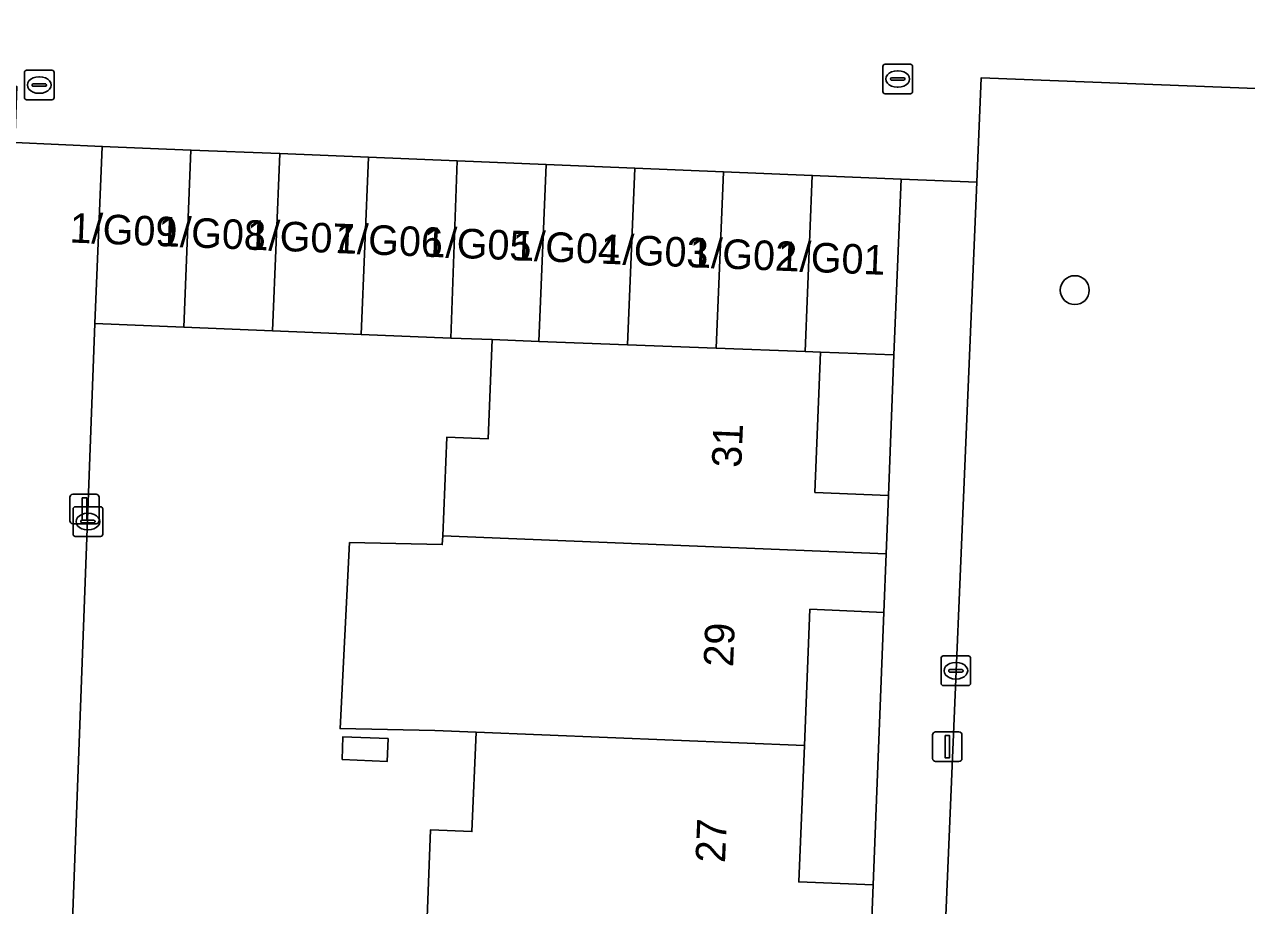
# Model space of a CAD drawing. Extents: x 160786 to 161429, y 386828 to 387485.
# Drawn here: x 160937.96 to 160979.3, y 387037.78 to 387067.6 of the extents above; entities that cross this region are included whole.
import ezdxf

# ---------------------------------------------------------------- set-up
doc = ezdxf.new("R2010")
doc.units = 0
for name, color, linetype in [('IMGEO_Boom', 7, 'Continuous'), ('IMGEO_Brandkraan', 7, 'Continuous'), ('IMGEO_Erf', 7, 'Continuous'), ('IMGEO_Groenvoorziening', 7, 'Continuous'), ('IMGEO_Kolk', 7, 'Continuous'), ('IMGEO_Lichtmast', 7, 'Continuous'), ('IMGEO_Pand', 7, 'Continuous'), ('IMGEO_Pand_nummerreeks', 7, 'Continuous'), ('IMGEO_Rijbaan_lokaal_open', 7, 'Continuous'), ('IMGEO_Rioolput', 7, 'Continuous'), ('IMGEO_Voetpad_open', 7, 'Continuous')]:
    doc.layers.add(name, color=color, linetype=linetype)

msp = doc.modelspace()

# ---------------------------------------------------------------- linework, layer by layer
at = {"layer": 'IMGEO_Boom'}
msp.add_circle((160973.488, 387058.606), 0.489, dxfattribs=at)
at = {"layer": 'IMGEO_Brandkraan'}
for p, q in [((160966.998, 387065.324), (160966.998, 387066.176)), ((160967.073, 387066.25), (160967.925, 387066.25)), ((160967.999, 387066.176), (160967.999, 387065.324)), ((160967.257, 387065.744), (160967.257, 387065.756)), ((160967.695, 387065.707), (160967.297, 387065.707)), ((160967.3, 387065.793), (160967.698, 387065.793)), ((160967.486, 387066.03), (160967.511, 387066.03)), ((160967.741, 387065.756), (160967.741, 387065.744)), ((160967.925, 387065.25), (160967.073, 387065.25)), ((160967.509, 387065.47), (160967.484, 387065.47))]:
    msp.add_line(p, q, dxfattribs=at)
for points in [[(160966.998, 387065.324), (160966.998, 387066.176)], [(160967.073, 387066.25), (160967.925, 387066.25)], [(160967.999, 387066.176), (160967.999, 387065.324)], [(160967.925, 387065.25), (160967.073, 387065.25)]]:
    msp.add_lwpolyline(points, dxfattribs=at)
for centre, radius, start, end in [((160967.075, 387066.174), 0.0765, 91.552, 178.448), ((160967.075, 387066.174), 0.0765, 91.552, 178.448), ((160967.923, 387066.174), 0.0765, 1.552, 88.448), ((160967.923, 387066.174), 0.0765, 1.552, 88.448), ((160967.297, 387065.753), 0.0403, 85.8775, 175.7526), ((160967.294, 387065.743), 0.0366, 178.938, 274.7102), ((160967.698, 387065.75), 0.043, 264.8664, 352.4533), ((160967.702, 387065.755), 0.0386, 1.7309, 96.639), ((160967.075, 387065.326), 0.0765, 181.552, 268.448), ((160967.075, 387065.326), 0.0765, 181.552, 268.448), ((160967.923, 387065.326), 0.0765, 271.552, 358.448), ((160967.923, 387065.326), 0.0765, 271.552, 358.448)]:
    msp.add_arc(centre, radius, start, end, dxfattribs=at)
for centre, major_axis, ratio, start_param, end_param in [((160967.485, 387065.75), (-0.387, 0.002), 0.722429, 4.712389, 7.853982), ((160967.51, 387065.75), (-0.39, 0.002), 0.717154, 1.570796, 4.712389)]:
    msp.add_ellipse(centre, major_axis=major_axis, ratio=ratio, start_param=start_param, end_param=end_param, dxfattribs=at)
at = {"layer": 'IMGEO_Erf'}
msp.add_lwpolyline([(160952.689, 387030.392), (160952.825, 387033.729), (160951.429, 387033.786), (160951.564, 387037.085), (160951.697, 387040.344), (160953.094, 387040.287), (160953.232, 387043.647), (160951.835, 387043.704), (160948.634, 387043.772), (160948.955, 387050.065), (160952.093, 387049.997), (160952.105, 387050.296), (160952.242, 387053.63), (160953.638, 387053.573), (160953.776, 387056.932), (160952.379, 387056.985), (160949.35, 387057.11), (160946.347, 387057.233), (160943.345, 387057.357), (160940.342, 387057.48), (160938.734, 387014.625), (160938.47, 387007.597)], dxfattribs=at)
for points in [[(160964.889, 387056.508), (160964.695, 387051.761), (160967.187, 387051.658), (160967.366, 387056.416)], [(160967.024, 387047.703), (160964.528, 387047.806), (160964.339, 387043.192), (160964.15, 387038.581), (160966.671, 387038.478)], [(160948.7, 387042.719), (160948.731, 387043.494), (160950.256, 387043.431), (160950.225, 387042.656)]]:
    msp.add_lwpolyline(points, close=True, dxfattribs=at)
at = {"layer": 'IMGEO_Groenvoorziening'}
msp.add_lwpolyline([(160981.974, 387001.361), (160984.552, 387065.241), (160970.32, 387065.784), (160970.17, 387062.263), (160967.621, 387001.944)], close=True, dxfattribs=at)
at = {"layer": 'IMGEO_Kolk'}
for p, q in [((160939.602, 387050.348), (160939.602, 387051.2)), ((160939.677, 387051.274), (160940.529, 387051.274)), ((160940.603, 387051.2), (160940.603, 387050.348)), ((160939.861, 387050.768), (160939.861, 387050.78)), ((160939.904, 387050.817), (160940.302, 387050.817)), ((160940.09, 387051.054), (160940.115, 387051.054)), ((160940.345, 387050.78), (160940.345, 387050.768)), ((160940.299, 387050.731), (160939.901, 387050.731)), ((160940.113, 387050.494), (160940.088, 387050.494)), ((160940.529, 387050.274), (160939.677, 387050.274)), ((160969.039, 387046.226), (160969.891, 387046.226)), ((160968.964, 387045.3), (160968.964, 387046.152)), ((160969.452, 387046.006), (160969.477, 387046.006)), ((160969.965, 387046.152), (160969.965, 387045.3)), ((160969.223, 387045.72), (160969.223, 387045.732)), ((160969.661, 387045.683), (160969.263, 387045.683)), ((160969.266, 387045.769), (160969.664, 387045.769)), ((160969.475, 387045.446), (160969.45, 387045.446)), ((160969.707, 387045.732), (160969.707, 387045.72)), ((160969.891, 387045.226), (160969.039, 387045.226))]:
    msp.add_line(p, q, dxfattribs=at)
for points in [[(160939.602, 387050.348), (160939.602, 387051.2)], [(160939.677, 387051.274), (160940.529, 387051.274)], [(160940.603, 387051.2), (160940.603, 387050.348)], [(160940.529, 387050.274), (160939.677, 387050.274)], [(160969.039, 387046.226), (160969.891, 387046.226)], [(160968.964, 387045.3), (160968.964, 387046.152)], [(160969.965, 387046.152), (160969.965, 387045.3)], [(160969.891, 387045.226), (160969.039, 387045.226)]]:
    msp.add_lwpolyline(points, dxfattribs=at)
for centre, radius, start, end in [((160939.679, 387051.198), 0.0765, 91.552, 178.448), ((160939.679, 387051.198), 0.0765, 91.552, 178.448), ((160940.527, 387051.198), 0.0765, 1.552, 88.448), ((160940.527, 387051.198), 0.0765, 1.552, 88.448), ((160939.901, 387050.777), 0.0403, 85.8775, 175.7526), ((160939.898, 387050.767), 0.0366, 178.938, 274.7102), ((160940.302, 387050.774), 0.043, 264.8664, 352.4533), ((160940.306, 387050.779), 0.0386, 1.7309, 96.639), ((160939.679, 387050.35), 0.0765, 181.552, 268.448), ((160939.679, 387050.35), 0.0765, 181.552, 268.448), ((160940.527, 387050.35), 0.0765, 271.552, 358.448), ((160940.527, 387050.35), 0.0765, 271.552, 358.448), ((160969.041, 387046.15), 0.0765, 91.552, 178.448), ((160969.041, 387046.15), 0.0765, 91.552, 178.448), ((160969.889, 387046.15), 0.0765, 1.552, 88.448), ((160969.889, 387046.15), 0.0765, 1.552, 88.448), ((160969.263, 387045.729), 0.0403, 85.8775, 175.7526), ((160969.26, 387045.719), 0.0366, 178.938, 274.7102), ((160969.664, 387045.726), 0.043, 264.8664, 352.4533), ((160969.668, 387045.731), 0.0386, 1.7309, 96.639), ((160969.041, 387045.302), 0.0765, 181.552, 268.448), ((160969.041, 387045.302), 0.0765, 181.552, 268.448), ((160969.889, 387045.302), 0.0765, 271.552, 358.448), ((160969.889, 387045.302), 0.0765, 271.552, 358.448)]:
    msp.add_arc(centre, radius, start, end, dxfattribs=at)
for centre, major_axis, ratio, start_param, end_param in [((160940.089, 387050.774), (-0.387, 0.002), 0.722429, 4.712389, 7.853982), ((160940.114, 387050.774), (-0.39, 0.002), 0.717154, 1.570796, 4.712389), ((160969.451, 387045.726), (-0.387, 0.002), 0.722429, 4.712389, 7.853982), ((160969.476, 387045.726), (-0.39, 0.002), 0.717154, 1.570796, 4.712389)]:
    msp.add_ellipse(centre, major_axis=major_axis, ratio=ratio, start_param=start_param, end_param=end_param, dxfattribs=at)
at = {"layer": 'IMGEO_Lichtmast'}
for p, q in [((160939.492, 387050.8), (160939.492, 387051.6)), ((160939.492, 387051.6), (160939.492, 387050.8)), ((160939.592, 387051.7), (160940.382, 387051.7)), ((160940.382, 387051.7), (160939.592, 387051.7)), ((160940.482, 387051.6), (160940.482, 387050.8)), ((160940.482, 387050.8), (160940.482, 387051.6)), ((160940.382, 387050.7), (160939.592, 387050.7)), ((160939.592, 387050.7), (160940.382, 387050.7)), ((160968.68, 387042.757), (160968.68, 387043.557)), ((160968.68, 387043.557), (160968.68, 387042.757)), ((160968.78, 387043.657), (160969.57, 387043.657)), ((160969.57, 387043.657), (160968.78, 387043.657)), ((160969.67, 387043.557), (160969.67, 387042.757)), ((160969.67, 387042.757), (160969.67, 387043.557)), ((160969.57, 387042.657), (160968.78, 387042.657)), ((160968.78, 387042.657), (160969.57, 387042.657))]:
    msp.add_line(p, q, dxfattribs=at)
for points in [[(160939.912, 387051.575), (160940.062, 387051.575), (160940.062, 387050.825), (160939.912, 387050.825), (160939.912, 387051.575)], [(160969.1, 387043.532), (160969.25, 387043.532), (160969.25, 387042.782), (160969.1, 387042.782), (160969.1, 387043.532)]]:
    msp.add_lwpolyline(points, dxfattribs=at)
for centre, start, end in [((160939.592, 387051.6), 90, 180), ((160939.592, 387051.6), 90, 180), ((160940.382, 387051.6), 0, 90), ((160940.382, 387051.6), 360, 90), ((160939.592, 387050.8), 180, 270), ((160939.592, 387050.8), 180, 270), ((160940.382, 387050.8), 270, 0), ((160940.382, 387050.8), 270, 0), ((160968.78, 387043.557), 90, 180), ((160968.78, 387043.557), 90, 180), ((160969.57, 387043.557), 0, 90), ((160969.57, 387043.557), 360, 90), ((160968.78, 387042.757), 180, 270), ((160968.78, 387042.757), 180, 270), ((160969.57, 387042.757), 270, 0), ((160969.57, 387042.757), 270, 0)]:
    msp.add_arc(centre, 0.1, start, end, dxfattribs=at)
at = {"layer": 'IMGEO_Pand'}
for points in [[(160943.345, 387057.357), (160943.59, 387063.347), (160940.588, 387063.47), (160940.342, 387057.48)], [(160946.593, 387063.224), (160943.59, 387063.347), (160943.345, 387057.357), (160946.347, 387057.233)], [(160946.347, 387057.233), (160949.35, 387057.11), (160949.595, 387063.101), (160946.593, 387063.224)], [(160949.35, 387057.11), (160952.379, 387056.985), (160952.598, 387062.978), (160949.595, 387063.101)], [(160955.6, 387062.855), (160952.598, 387062.978), (160952.379, 387056.985), (160953.776, 387056.932), (160955.355, 387056.872)], [(160958.603, 387062.732), (160955.6, 387062.855), (160955.355, 387056.872), (160958.358, 387056.758)], [(160961.605, 387062.609), (160958.603, 387062.732), (160958.358, 387056.758), (160961.361, 387056.644)], [(160961.361, 387056.644), (160964.364, 387056.53), (160964.608, 387062.486), (160961.605, 387062.609)], [(160967.61, 387062.363), (160964.608, 387062.486), (160964.364, 387056.53), (160964.889, 387056.508), (160967.366, 387056.416)], [(160964.889, 387056.508), (160964.364, 387056.53), (160961.361, 387056.644), (160958.358, 387056.758), (160955.355, 387056.872), (160953.776, 387056.932), (160953.638, 387053.573), (160952.242, 387053.63), (160952.105, 387050.296), (160967.106, 387049.682), (160967.187, 387051.658), (160964.695, 387051.761)], [(160964.528, 387047.806), (160967.024, 387047.703), (160967.106, 387049.682), (160952.105, 387050.296), (160952.093, 387049.997), (160948.955, 387050.065), (160948.634, 387043.772), (160951.835, 387043.704), (160953.232, 387043.647), (160964.339, 387043.192)], [(160948.7, 387042.719), (160950.225, 387042.656), (160950.256, 387043.431), (160948.731, 387043.494)], [(160964.339, 387043.192), (160953.232, 387043.647), (160953.094, 387040.287), (160951.697, 387040.344), (160951.564, 387037.085), (160966.589, 387036.47), (160966.671, 387038.478), (160964.15, 387038.581)]]:
    msp.add_lwpolyline(points, close=True, dxfattribs=at)
at = {"layer": 'IMGEO_Rijbaan_lokaal_open'}
msp.add_lwpolyline([(160885.404, 387067.596), (160898.67, 387067.06), (160901.451, 387066.947), (160916.73, 387066.33), (160919.396, 387066.234), (160934.813, 387065.611), (160937.702, 387065.494), (160937.626, 387063.606), (160940.588, 387063.47), (160943.59, 387063.347), (160946.593, 387063.224), (160949.595, 387063.101), (160952.598, 387062.978), (160955.6, 387062.855), (160958.603, 387062.732), (160961.605, 387062.609), (160964.608, 387062.486), (160967.61, 387062.363), (160970.17, 387062.263), (160970.32, 387065.784), (160984.552, 387065.241)], dxfattribs=at)
at = {"layer": 'IMGEO_Rioolput'}
for p, q in [((160938.031, 387066.045), (160938.883, 387066.045)), ((160937.956, 387065.119), (160937.956, 387065.971)), ((160938.444, 387065.825), (160938.469, 387065.825)), ((160938.957, 387065.971), (160938.957, 387065.119)), ((160938.215, 387065.539), (160938.215, 387065.551)), ((160938.653, 387065.502), (160938.255, 387065.502)), ((160938.258, 387065.588), (160938.656, 387065.588)), ((160938.467, 387065.265), (160938.442, 387065.265)), ((160938.699, 387065.551), (160938.699, 387065.539)), ((160938.883, 387065.045), (160938.031, 387065.045))]:
    msp.add_line(p, q, dxfattribs=at)
for points in [[(160938.031, 387066.045), (160938.883, 387066.045)], [(160937.956, 387065.119), (160937.956, 387065.971)], [(160938.957, 387065.971), (160938.957, 387065.119)], [(160938.883, 387065.045), (160938.031, 387065.045)]]:
    msp.add_lwpolyline(points, dxfattribs=at)
for centre, radius, start, end in [((160938.033, 387065.969), 0.0765, 91.552, 178.448), ((160938.033, 387065.969), 0.0765, 91.552, 178.448), ((160938.881, 387065.969), 0.0765, 1.552, 88.448), ((160938.881, 387065.969), 0.0765, 1.552, 88.448), ((160938.255, 387065.548), 0.0403, 85.8775, 175.7526), ((160938.252, 387065.538), 0.0366, 178.938, 274.7102), ((160938.656, 387065.545), 0.043, 264.8664, 352.4533), ((160938.66, 387065.55), 0.0386, 1.7309, 96.639), ((160938.033, 387065.121), 0.0765, 181.552, 268.448), ((160938.033, 387065.121), 0.0765, 181.552, 268.448), ((160938.881, 387065.121), 0.0765, 271.552, 358.448), ((160938.881, 387065.121), 0.0765, 271.552, 358.448)]:
    msp.add_arc(centre, radius, start, end, dxfattribs=at)
for centre, major_axis, ratio, start_param, end_param in [((160938.443, 387065.545), (-0.387, 0.002), 0.722429, 4.712389, 7.853982), ((160938.468, 387065.545), (-0.39, 0.002), 0.717154, 1.570796, 4.712389)]:
    msp.add_ellipse(centre, major_axis=major_axis, ratio=ratio, start_param=start_param, end_param=end_param, dxfattribs=at)
at = {"layer": 'IMGEO_Voetpad_open'}
for points in [[(160937.126, 387051.542), (160936.884, 387045.544), (160936.491, 387033.349), (160936.116, 387024.42), (160935.762, 387014.709), (160938.734, 387014.625), (160940.342, 387057.48), (160940.588, 387063.47), (160937.626, 387063.606), (160937.46, 387059.492)], [(160967.366, 387056.416), (160967.187, 387051.658), (160967.106, 387049.682), (160967.024, 387047.703), (160966.671, 387038.478), (160966.589, 387036.47), (160966.506, 387034.458), (160966.132, 387025.212), (160966.052, 387023.258), (160965.972, 387021.303), (160965.597, 387012.037), (160965.516, 387010.052), (160965.435, 387008.068), (160965.254, 387000.768), (160967.568, 387000.672), (160967.621, 387001.944), (160970.17, 387062.263), (160967.61, 387062.363)]]:
    msp.add_lwpolyline(points, close=True, dxfattribs=at)

# ---------------------------------------------------------------- texts
at = {"layer": 'IMGEO_Pand_nummerreeks'}
for s, rotation, p in [('1/G09', 357.7217, (160939.471, 387060.219)), ('1/G08', 357.7217, (160942.466, 387060.1)), ('1/G07', 357.7217, (160945.46, 387059.981)), ('1/G06', 357.7217, (160948.454, 387059.862)), ('1/G05', 357.7196, (160951.449, 387059.742)), ('1/G04', 357.7217, (160954.443, 387059.623)), ('1/G03', 357.7217, (160957.438, 387059.504)), ('1/G02', 357.7217, (160960.432, 387059.385)), ('1/G01', 357.7217, (160963.426, 387059.266)), ('31', 87.6454, (160962.205, 387052.585)), ('29', 87.6454, (160961.928, 387045.843)), ('27', 87.6454, (160961.655, 387039.214))]:
    msp.add_text(s, height=1, rotation=rotation, dxfattribs=at).set_placement(p)

doc.saveas('drawing.dxf')
